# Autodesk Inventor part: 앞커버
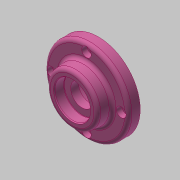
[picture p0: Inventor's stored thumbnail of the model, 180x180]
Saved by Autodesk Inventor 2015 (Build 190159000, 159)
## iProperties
Created: 2017-08
Part Number: 앞커버
Material: 알루미늄 6061
Document SubType Name: Modeling
Designer: mduedu
Density: 1 g/cm^3
Appearance: 분홍색
Author: mduedu
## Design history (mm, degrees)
sketch "스케치1"
  geometry: C1 r 35 at (0, 0); 1 further point
  constraints: 1 centre point, 1 coincident
  dimensions: "d0" = 70 diameter of C1
extrude "돌출1" new body sketch "스케치1" distance "d1" = 10; taper "d2" = 0 deg
sketch "스케치2"
  geometry: C1 r 22 at (0, 0); 1 further point
  constraints: 1 centre point, 1 coincident
  dimensions: "d3" = 44 diameter of C1
node "작업 평면1"
sketch "스케치3"
  geometry: C1 r 21 at (0, 0); 1 further point
  constraints: 1 centre point, 1 coincident
  dimensions: "d5" = 42 diameter of C1
feature "로프트1" sketch "스케치3" dims "d6" = 0, "d7" = 90 deg, "d8" = 0, "d9" = 90 deg
sketch "스케치4"
  geometry: C1 r 24 at (0, 0); 1 further point
  constraints: 1 centre point, 1 coincident
  dimensions: "d86" = 48 diameter of C1
extrude "돌출2" join sketch "스케치4" distance "d10" = 8; taper "d11" = 0 deg
hole "구멍1" diameter "d14" = 40; stored, may be unused: countersink angle "d18" = 90 deg, drill point angle "d20" = 0 deg; dims "d15" = 6, "d16" = 4, "d17" = 2, "d19" = 12, "d87" = 10, "d88" = 10
hole "구멍2" diameter "d23" = 34; stored, may be unused: countersink angle "d27" = 90 deg, drill point angle "d29" = 0 deg; dims "d21" = 10, "d22" = 10, "d24" = 6, "d25" = 4, "d26" = 2, "d28" = 3
hole "구멍3" diameter "d32" = 19; stored, may be unused: countersink angle "d36" = 90 deg, drill point angle "d38" = 0 deg; dims "d30" = 10, "d31" = 10, "d33" = 6, "d34" = 4, "d35" = 2, "d37" = 3
chamfer "모따기1" distance "d39" = 1; stored, may be unused: second distance "d40" = 2, angle "d41" = 45 deg
sketch "스케치5"
  geometry: C1 r 15 at (0, 0); 1 further point
  constraints: 1 centre point, 1 coincident
  dimensions: "d42" = 30 diameter of C1
extrude "돌출3" cut sketch "스케치5" distance "d43" = 8.3; taper "d44" = 0 deg
chamfer "모따기2" distance "d47" = 0.8; stored, may be unused: second distance "d48" = 2, angle "d49" = 30 deg
fillet "모깎기1" dims "d50" = 0.3
fillet "모깎기2" dims "d51" = 0.3
fillet "모깎기3" dims "d52" = 3
sketch "스케치6" dims "d53" = 58
  geometry: 6 further points
  constraints: 2 vertical alignment, 1 coincident, 7 other
  dimensions: "d56" = 360 deg dimension on point (0, 0) point (0, 29) (derived)
sketch "스케치9" dims "d85" = 58 (derived)
  geometry: 6 further points
  constraints: 1 coincident, 1 vertical alignment, 6 other
hole "구멍6" sketch "스케치9" at (-29, 0), (0, -29), (29, 0), (0, 29) diameter "d72" = 4.5; stored, may be unused: countersink angle "d76" = 90 deg, drill point angle "d78" = 0 deg; dims "d73" = 6, "d74" = 8, "d75" = 4.6, "d77" = 8
fillet "모깎기4" dims "d79" = 3
fillet "모깎기5" dims "d80" = 3
fillet "모깎기6" dims "d81" = 3
node "솔리드1"
other parameters: "d4" = 12
